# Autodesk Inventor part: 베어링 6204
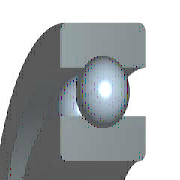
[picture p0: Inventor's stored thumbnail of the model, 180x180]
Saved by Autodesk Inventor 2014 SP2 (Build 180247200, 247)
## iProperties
IsCustomPart: 0
Created: 2018-09
Part Number: 베어링 6204
Material: 스테인리스강
Description: 깊은 그루브 볼 베어링
Document SubType Name: Modeling
Standard: KS B 2023
Standards Organization: KS
Language: ko-KR
Size Designation: 6204 - 20 x 47 x 14
Categories: <MemberInstance><Categories><Category DisplayName="샤프트 부품" InternalName="7f7aeb1f-a693-4053-b835-cee3144e0d98" Mnemonic="SHFT"><Category DisplayName="베어링" Inter
Density: 8.08 g/cm^3
Mass: 107.173 g
Surface Area: 87.8912 cm^2
Volume: 13.264 cm^3
Appearance: 노란색
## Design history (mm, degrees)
sketch "스케치" dims "d0" = 7.02 (= -0.26 x WD + 0.26 x BD)
  geometry: L1 (3.49, 16.75)-(10.51, 16.75); L2 (7, 16.75)-(7, 13.24); L3 (7, 16.75)-(7, 20.26); L4 (4.392, 14.401)-(0, 14.401); L5 (0, 10)-(14, 10); L6 (4.392, 19.099)-(0, 19.099); L7 (0, 23.5)-(14, 23.5); L8 (14, 10)-(14, 14.401); L9 (9.608, 14.401)-(14, 14.401); L10 (9.608, 19.099)-(14, 19.099); L11 (14, 23.5)-(14, 19.099); L12 (-1.4, 0)-(8.4, 0) reference; L13 (0, -0.3)-(0, 5.3) reference
  constraints: 22 end point, 4 point on line, 2 collinear, 2 perpendicular, 2 symmetric about line, 1 midpoint, 1 parallel, 14 other
  dimensions: "d9" = 20 diameter of L5 L12 (= WD); "d11" = 47 diameter of L7 L12 (= BD); "d12" = 14 distance between parallel lines of L8 L13 (= KB); "d13" = 28.802 diameter of L9 L12 (= 0.326 x BD + 0.674 x WD)
revolve "본체" stored, may be unused: angle "d6" = 90 deg
revolve "볼" stored, may be unused: angle "d7" = 90 deg
pattern_circular "IDS_ARRAYBALL[SIMPL:T]" dims angle "d3" = 360 deg
body "Solid1"
fillet "모깎기1" dims "d1" = 1 (= KRS)
other parameters: "WD" = 20 [user parameter; used in 5 equation terms], "BD" = 47 [user parameter; used in 5 equation terms], "KB" = 14 [user parameter; used in 1 equation term], "KRS" = 1 [user parameter; used in 1 equation term], "d4" = 0, "d5" = 0, "d8" = 0, "d14" = 0, "d15" = 0, "BBA" = 0 [user parameter], "BC0" = 6550000 [user parameter], "BC" = 1.27e+07 [user parameter], "BR" = 23.5 (= 0.5 x BD) [user parameter]
